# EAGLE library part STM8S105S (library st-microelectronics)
Access line, 16 MHz STM8S 8-bit MCU up to 32 Kbytes Flash, integrated EEPROM,10-bit ADC, timers, UART, SPI, I²C Source: Data sheet
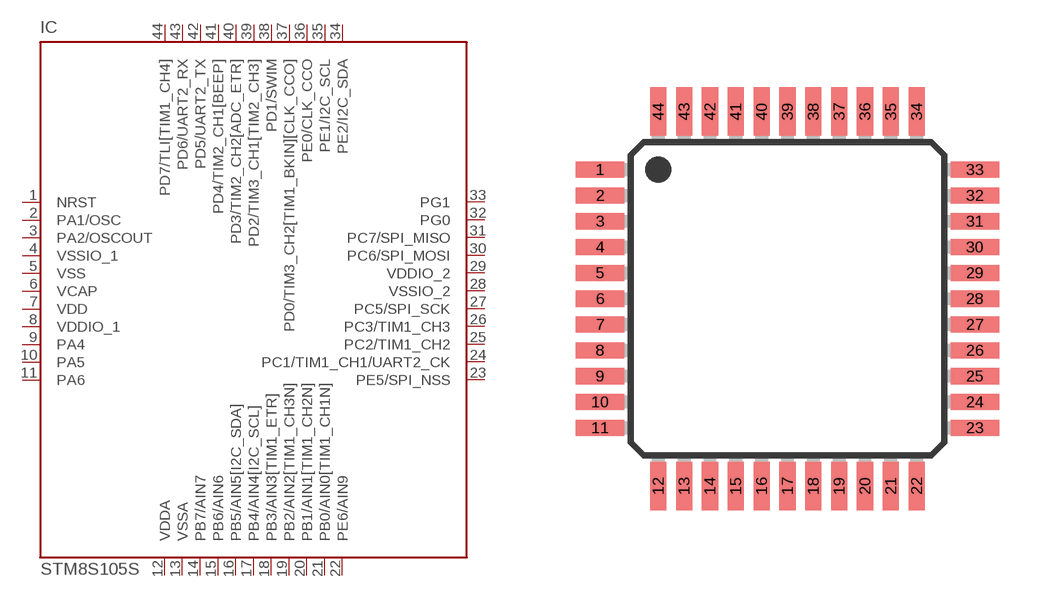
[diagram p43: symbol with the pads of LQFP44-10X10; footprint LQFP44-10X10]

Designator prefix IC

## STM8S105S4 (MPN: STM8S105S4T6C; OC_FARNELL: 1706227; OC_NEWARK: 09R6037), STM8S105S6 (MPN: STM8S105S6T6C; OC_FARNELL: 1706228; OC_NEWARK: 09R6038)  [LQFP44-10X10]
1  NRST
2  PA1/OSC
3  PA2/OSCOUT
4  VSSIO_1  pwr
5  VSS  pwr
6  VCAP  pwr
7  VDD  pwr
8  VDDIO_1  pwr
9  PA4
10  PA5
11  PA6
12  VDDA  pwr
13  VSSA  pwr
14  PB7/AIN7
15  PB6/AIN6
16  PB5/AIN5[I2C_SDA]
17  PB4/AIN4[I2C_SCL]
18  PB3/AIN3[TIM1_ETR]
19  PB2/AIN2[TIM1_CH3N]
20  PB1/AIN1[TIM1_CH2N]
21  PB0/AIN0[TIM1_CH1N]
22  PE6/AIN9
23  PE5/SPI_NSS
24  PC1/TIM1_CH1/UART2_CK
25  PC2/TIM1_CH2
26  PC3/TIM1_CH3
27  PC5/SPI_SCK
28  VSSIO_2  pwr
29  VDDIO_2  pwr
30  PC6/SPI_MOSI
31  PC7/SPI_MISO
32  PG0
33  PG1
34  PE2/I2C_SDA
35  PE1/I2C_SCL
36  PE0/CLK_CCO
37  PD0/TIM3_CH2[TIM1_BKIN][CLK_CCO]
38  PD1/SWIM
39  PD2/TIM3_CH1[TIM2_CH3]
40  PD3/TIM2_CH2[ADC_ETR]
41  PD4/TIM2_CH1[BEEP]
42  PD5/UART2_TX
43  PD6/UART2_RX
44  PD7/TLI[TIM1_CH4]

## Footprint LQFP44-10X10 (pad centres in mm)
44-pin low profile quad flat package 10 x 10 mm Source: Data sheet
smd 1.5 x 0.5: 1 -5.8,4; 2 -5.8,3.2; 3 -5.8,2.4; 4 -5.8,1.6; 5 -5.8,0.8; 6 -5.8,0; 7 -5.8,-0.8; 8 -5.8,-1.6; 9 -5.8,-2.4; 10 -5.8,-3.2; 11 -5.8,-4; 23 5.8,-4; 24 5.8,-3.2; 25 5.8,-2.4; 26 5.8,-1.6; 27 5.8,-0.8; 28 5.8,0; 29 5.8,0.8; 30 5.8,1.6; 31 5.8,2.4; 32 5.8,3.2; 33 5.8,4
smd 0.5 x 1.5: 12 -4,-5.8; 13 -3.2,-5.8; 14 -2.4,-5.8; 15 -1.6,-5.8; 16 -0.8,-5.8; 17 0,-5.8; 18 0.8,-5.8; 19 1.6,-5.8; 20 2.4,-5.8; 21 3.2,-5.8; 22 4,-5.8; 34 4,5.8; 35 3.2,5.8; 36 2.4,5.8; 37 1.6,5.8; 38 0.8,5.8; 39 0,5.8; 40 -0.8,5.8; 41 -1.6,5.8; 42 -2.4,5.8; 43 -3.2,5.8; 44 -4,5.8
